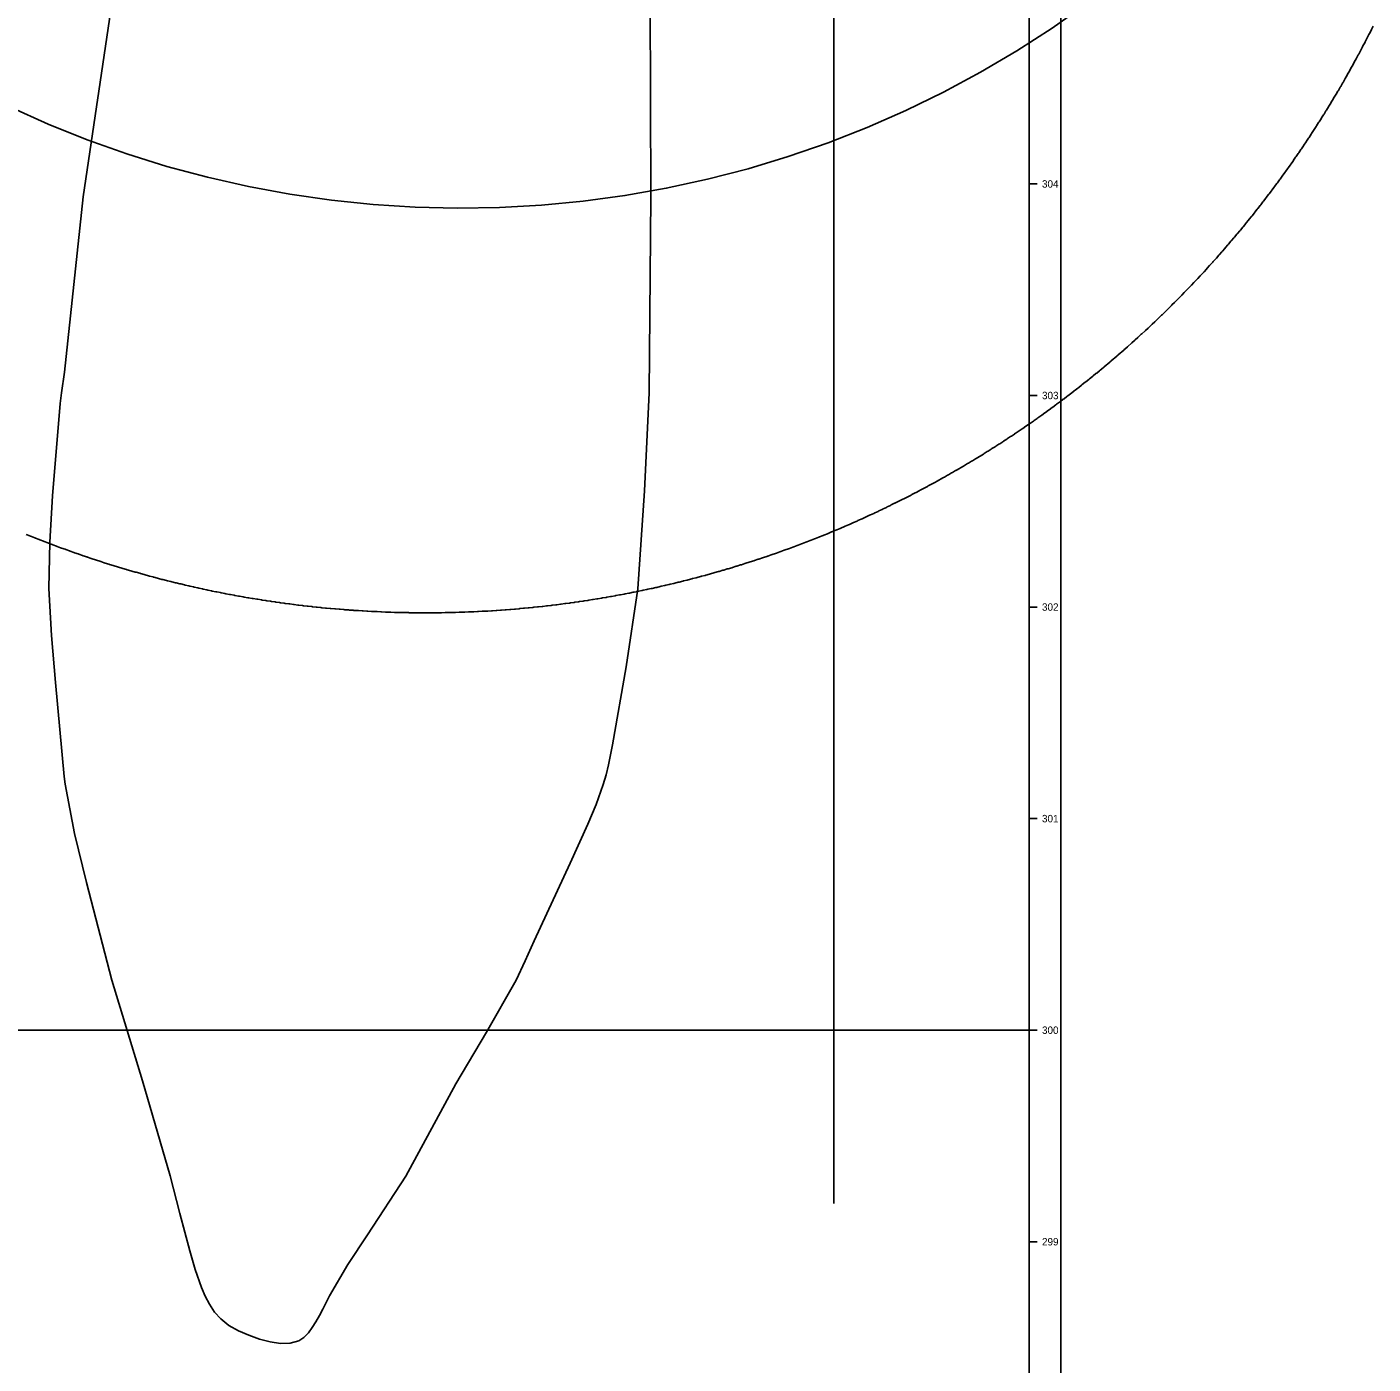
# Model space of a CAD drawing. Extents: x 468834 to 503362, y 294936 to 320859.
# Drawn here: x 496187 to 502549, y 298422 to 304742 of the extents above; entities that cross this region are included whole.
import ezdxf

# ---------------------------------------------------------------- set-up
doc = ezdxf.new("R2010")
doc.units = 0
for name, color, linetype in [('1020106_TIN16_5 km radiuss ap lidlauku Rīga kontrolpunktu', 7, 'Continuous'), ('1020107_TIN17_5 km radiuss ap lidlauku Rīga slieksniem', 7, 'Continuous'), ('1020110_TIN110_Lidmašīnu radīto trokšņu robežlieluma pārsnieguma teritorija', 7, 'Continuous'), ('ramis', 7, 'Continuous')]:
    doc.layers.add(name, color=color, linetype=linetype)

msp = doc.modelspace()

# ---------------------------------------------------------------- linework, layer by layer
at = {"layer": '1020106_TIN16_5 km radiuss ap lidlauku Rīga kontrolpunktu'}
msp.add_lwpolyline([(501194.7, 304851), (501032.1, 304736.8), (500865, 304629.1), (500693.8, 304528.1), (500518.8, 304434.1), (500340.1, 304347.1), (500158.1, 304267.2), (499973.1, 304194.7), (499785.3, 304129.5), (499595.1, 304071.9), (499402.7, 304021.9), (499208.6, 303979.6), (499012.9, 303945), (498815.9, 303918.2), (498618.1, 303899.3), (498419.7, 303888.3), (498220.9, 303885.1), (498022.3, 303889.9), (497823.9, 303902.6), (497626.2, 303923.1), (497429.5, 303951.5), (497234.1, 303987.7), (497040.3, 304031.6), (496848.3, 304083.2), (496658.6, 304142.3), (496471.4, 304209), (496287, 304283.1), (496105.6, 304364.4)], dxfattribs=at)
at = {"layer": '1020107_TIN17_5 km radiuss ap lidlauku Rīga slieksniem'}
msp.add_lwpolyline([(502549.4, 304745.6), (502541.6, 304730), (502539.6, 304726.1), (502531.7, 304710.5), (502529.7, 304706.6), (502521.8, 304691.1), (502519.8, 304687.2), (502511.8, 304671.7), (502509.8, 304667.8), (502501.7, 304652.3), (502499.7, 304648.5), (502491.6, 304633), (502489.5, 304629.2), (502481.3, 304613.8), (502479.2, 304609.9), (502471, 304594.6), (502468.9, 304590.7), (502460.6, 304575.4), (502458.5, 304571.6), (502450, 304556.3), (502447.9, 304552.5), (502439.5, 304537.2), (502437.3, 304533.4), (502428.8, 304518.2), (502426.6, 304514.4), (502418, 304499.2), (502415.9, 304495.4), (502407.2, 304480.2), (502405.5, 304477.3), (502405, 304476.5), (502396.3, 304461.4), (502394.1, 304457.6), (502385.3, 304442.5), (502383.1, 304438.8), (502374.2, 304423.7), (502372, 304420), (502363, 304405), (502360.8, 304401.2), (502351.8, 304386.3), (502349.5, 304382.6), (502340.5, 304367.6), (502338.2, 304363.9), (502329.1, 304349), (502326.8, 304345.3), (502317.6, 304330.5), (502315.3, 304326.8), (502306, 304312), (502303.7, 304308.3), (502294.4, 304293.6), (502292, 304289.9), (502282.6, 304275.2), (502280.3, 304271.5), (502270.8, 304256.8), (502268.4, 304253.2), (502258.9, 304238.5), (502256.5, 304234.9), (502246.9, 304220.3), (502244.5, 304216.6), (502234.9, 304202.1), (502233, 304199.2), (502232.5, 304198.5), (502222.8, 304184), (502220.3, 304180.3), (502210.6, 304165.9), (502208.1, 304162.3), (502198.3, 304147.9), (502195.8, 304144.3), (502185.9, 304129.9), (502183.4, 304126.3), (502173.5, 304112), (502171, 304108.4), (502160.9, 304094.1), (502158.4, 304090.5), (502148.3, 304076.3), (502145.8, 304072.7), (502135.7, 304058.5), (502133.1, 304055), (502122.9, 304040.8), (502120.3, 304037.3), (502110.1, 304023.2), (502107.5, 304019.7), (502097.2, 304005.6), (502094.6, 304002.1), (502084.2, 303988.1), (502081.6, 303984.6), (502071.1, 303970.6), (502068.5, 303967.1), (502058, 303953.2), (502055.3, 303949.7), (502044.8, 303935.8), (502042.7, 303933.1), (502042.1, 303932.4), (502031.5, 303918.5), (502028.8, 303915.1), (502018.1, 303901.3), (502015.4, 303897.8), (502004.7, 303884.1), (502002, 303880.7), (501991.2, 303867), (501988.4, 303863.5), (501977.6, 303849.9), (501974.8, 303846.5), (501963.9, 303832.9), (501961.2, 303829.5), (501950.2, 303815.9), (501947.4, 303812.6), (501936.4, 303799.1), (501933.6, 303795.7), (501922.5, 303782.2), (501919.7, 303778.9), (501908.5, 303765.5), (501905.7, 303762.1), (501894.5, 303748.8), (501891.7, 303745.4), (501880.4, 303732.1), (501877.5, 303728.8), (501866.2, 303715.5), (501863.4, 303712.2), (501852, 303699), (501849.1, 303695.7), (501837.6, 303682.5), (501835.4, 303680), (501834.8, 303679.3), (501823.2, 303666.2), (501820.4, 303662.9), (501808.8, 303649.8), (501805.9, 303646.6), (501794.2, 303633.6), (501791.3, 303630.3), (501779.6, 303617.3), (501776.7, 303614.1), (501765, 303601.2), (501762, 303598), (501750.2, 303585.1), (501747.3, 303581.9), (501735.4, 303569.1), (501732.4, 303565.9), (501720.5, 303553.2), (501717.5, 303550), (501705.6, 303537.3), (501702.6, 303534.1), (501690.5, 303521.5), (501687.5, 303518.3), (501675.4, 303505.7), (501672.4, 303502.6), (501660.3, 303490), (501657.2, 303486.9), (501645, 303474.4), (501642, 303471.3), (501629.7, 303458.9), (501626.7, 303455.7), (501614.4, 303443.4), (501611.9, 303440.9), (501611.3, 303440.3), (501598.9, 303427.9), (501595.8, 303424.9), (501583.4, 303412.6), (501580.3, 303409.5), (501567.9, 303397.3), (501564.7, 303394.3), (501552.2, 303382.1), (501549.1, 303379.1), (501536.5, 303366.9), (501533.4, 303363.9), (501520.8, 303351.9), (501517.6, 303348.9), (501504.9, 303336.9), (501501.8, 303333.9), (501489, 303321.9), (501485.8, 303318.9), (501473.1, 303307), (501469.9, 303304.1), (501457, 303292.2), (501453.8, 303289.3), (501441, 303277.5), (501437.7, 303274.6), (501424.8, 303262.9), (501421.6, 303259.9), (501408.6, 303248.3), (501405.3, 303245.4), (501392.3, 303233.7), (501389, 303230.8), (501375.9, 303219.3), (501373.4, 303217), (501372.7, 303216.4), (501359.5, 303204.9), (501356.2, 303202.1), (501343.1, 303190.6), (501339.8, 303187.8), (501326.5, 303176.4), (501323.2, 303173.5), (501309.9, 303162.2), (501306.6, 303159.4), (501293.3, 303148.1), (501289.9, 303145.3), (501276.6, 303134.1), (501273.2, 303131.3), (501259.8, 303120.2), (501256.4, 303117.4), (501242.9, 303106.3), (501239.6, 303103.5), (501226, 303092.5), (501222.6, 303089.8), (501209.1, 303078.8), (501205.7, 303076.1), (501192.1, 303065.1), (501188.6, 303062.4), (501175, 303051.6), (501171.5, 303048.9), (501157.8, 303038.1), (501154.4, 303035.4), (501140.6, 303024.6), (501137.2, 303022), (501123.4, 303011.3), (501120.7, 303009.2), (501119.9, 303008.6), (501106.1, 302998), (501102.6, 302995.4), (501088.7, 302984.8), (501085.2, 302982.2), (501071.3, 302971.7), (501067.8, 302969.1), (501053.8, 302958.7), (501050.3, 302956.1), (501036.2, 302945.7), (501032.7, 302943.1), (501018.6, 302932.8), (501015.1, 302930.2), (501001, 302920), (500997.4, 302917.4), (500983.3, 302907.3), (500979.7, 302904.7), (500965.5, 302894.6), (500961.9, 302892.1), (500947.7, 302882), (500944.1, 302879.5), (500929.8, 302869.5), (500926.2, 302867), (500911.9, 302857.1), (500908.3, 302854.6), (500893.9, 302844.7), (500890.3, 302842.3), (500875.8, 302832.5), (500872.2, 302830), (500857.7, 302820.3), (500854.9, 302818.4), (500854.1, 302817.8), (500839.6, 302808.2), (500836, 302805.7), (500821.4, 302796.1), (500817.8, 302793.7), (500803.2, 302784.2), (500799.5, 302781.8), (500784.8, 302772.3), (500781.2, 302769.9), (500766.5, 302760.5), (500762.8, 302758.2), (500748.1, 302748.8), (500744.4, 302746.5), (500729.6, 302737.2), (500725.9, 302734.8), (500711.1, 302725.6), (500707.4, 302723.3), (500692.6, 302714.1), (500688.8, 302711.9), (500674, 302702.7), (500670.2, 302700.5), (500655.3, 302691.4), (500651.6, 302689.2), (500636.6, 302680.2), (500632.8, 302678), (500617.8, 302669.1), (500614.1, 302666.8), (500599, 302658), (500595.3, 302655.8), (500580.2, 302647), (500577.2, 302645.3), (500576.4, 302644.8), (500561.3, 302636.1), (500557.5, 302633.9), (500542.3, 302625.3), (500538.5, 302623.1), (500523.3, 302614.6), (500519.5, 302612.4), (500504.3, 302603.9), (500500.5, 302601.8), (500485.2, 302593.3), (500481.4, 302591.2), (500466.1, 302582.9), (500462.3, 302580.8), (500446.9, 302572.5), (500443.1, 302570.4), (500427.7, 302562.1), (500423.8, 302560.1), (500408.4, 302551.9), (500404.6, 302549.9), (500389.1, 302541.8), (500385.2, 302539.7), (500369.8, 302531.7), (500365.9, 302529.7), (500350.4, 302521.7), (500346.5, 302519.7), (500330.9, 302511.8), (500327, 302509.9), (500311.4, 302502), (500307.5, 302500.1), (500291.9, 302492.3), (500288.8, 302490.8), (500288, 302490.4), (500272.3, 302482.7), (500268.4, 302480.7), (500252.7, 302473.1), (500248.8, 302471.2), (500233.1, 302463.6), (500229.1, 302461.7), (500213.4, 302454.2), (500209.4, 302452.4), (500193.6, 302444.9), (500189.7, 302443.1), (500173.8, 302435.7), (500169.9, 302433.9), (500154, 302426.6), (500150.1, 302424.8), (500134.2, 302417.6), (500130.2, 302415.8), (500114.3, 302408.6), (500110.3, 302406.8), (500094.3, 302399.8), (500090.3, 302398), (500074.4, 302391), (500070.4, 302389.2), (500054.4, 302382.3), (500050.3, 302380.6), (500034.3, 302373.7), (500030.3, 302372), (500014.2, 302365.2), (500010.2, 302363.5), (499994.1, 302356.8), (499990.9, 302355.4), (499990.1, 302355.1), (499973.9, 302348.4), (499969.9, 302346.8), (499953.7, 302340.2), (499949.7, 302338.5), (499933.5, 302332), (499929.5, 302330.4), (499913.2, 302323.9), (499909.2, 302322.3), (499892.9, 302315.9), (499888.9, 302314.4), (499872.6, 302308), (499868.5, 302306.5), (499852.2, 302300.2), (499848.2, 302298.7), (499831.8, 302292.5), (499827.7, 302291), (499811.4, 302284.9), (499807.3, 302283.4), (499790.9, 302277.3), (499786.8, 302275.8), (499770.4, 302269.9), (499766.3, 302268.4), (499749.9, 302262.5), (499745.8, 302261.1), (499729.3, 302255.3), (499725.2, 302253.8), (499708.7, 302248.1), (499704.6, 302246.6), (499688.1, 302241), (499684.8, 302239.9), (499683.9, 302239.6), (499667.4, 302234), (499663.3, 302232.6), (499646.7, 302227.1), (499642.6, 302225.7), (499626, 302220.2), (499621.8, 302218.9), (499605.2, 302213.5), (499601.1, 302212.2), (499584.5, 302206.9), (499580.3, 302205.6), (499563.7, 302200.3), (499559.5, 302199), (499542.8, 302193.9), (499538.6, 302192.6), (499521.9, 302187.5), (499517.8, 302186.2), (499501.1, 302181.2), (499496.9, 302180), (499480.1, 302175), (499475.9, 302173.8), (499459.2, 302168.9), (499455, 302167.7), (499438.2, 302162.9), (499434, 302161.7), (499417.2, 302157), (499413, 302155.8), (499396.2, 302151.2), (499392, 302150), (499375.1, 302145.5), (499371.8, 302144.6), (499370.9, 302144.3), (499354.1, 302139.8), (499349.8, 302138.7), (499333, 302134.3), (499328.7, 302133.2), (499311.8, 302128.8), (499307.6, 302127.8), (499290.7, 302123.5), (499286.5, 302122.4), (499269.5, 302118.2), (499265.3, 302117.2), (499248.3, 302113), (499244.1, 302112), (499227.1, 302108), (499222.9, 302106.9), (499205.9, 302103), (499201.6, 302102), (499184.6, 302098.1), (499180.4, 302097.1), (499163.3, 302093.3), (499159.1, 302092.3), (499142, 302088.5), (499137.8, 302087.6), (499120.7, 302083.9), (499116.4, 302083), (499099.4, 302079.4), (499095.1, 302078.5), (499078, 302075), (499073.7, 302074.1), (499056.6, 302070.6), (499053.2, 302070), (499052.3, 302069.8), (499035.2, 302066.4), (499030.9, 302065.5), (499013.8, 302062.2), (499009.5, 302061.4), (498992.4, 302058.2), (498988.1, 302057.4), (498970.9, 302054.2), (498966.6, 302053.4), (498949.4, 302050.3), (498945.1, 302049.6), (498928, 302046.6), (498923.7, 302045.8), (498906.4, 302042.9), (498902.1, 302042.2), (498884.9, 302039.3), (498880.6, 302038.6), (498863.4, 302035.8), (498859.1, 302035.1), (498841.8, 302032.4), (498837.5, 302031.7), (498820.3, 302029.1), (498816, 302028.4), (498798.7, 302025.9), (498794.4, 302025.2), (498777.1, 302022.7), (498772.8, 302022.1), (498755.5, 302019.7), (498751.2, 302019.1), (498733.9, 302016.8), (498730.5, 302016.3), (498729.6, 302016.2), (498712.3, 302014), (498707.9, 302013.4), (498690.6, 302011.2), (498686.3, 302010.7), (498669, 302008.6), (498664.6, 302008), (498647.3, 302006), (498643, 302005.5), (498625.6, 302003.5), (498621.3, 302003.1), (498603.9, 302001.2), (498599.6, 302000.7), (498582.2, 301998.9), (498577.9, 301998.5), (498560.5, 301996.7), (498556.2, 301996.3), (498538.8, 301994.7), (498534.5, 301994.3), (498517.1, 301992.7), (498512.7, 301992.3), (498495.3, 301990.8), (498491, 301990.4), (498473.6, 301989), (498469.2, 301988.6), (498451.8, 301987.3), (498447.5, 301987), (498430.1, 301985.7), (498425.7, 301985.4), (498408.3, 301984.2), (498404.9, 301983.9), (498404, 301983.9), (498386.6, 301982.7), (498382.2, 301982.5), (498364.8, 301981.4), (498360.4, 301981.2), (498343, 301980.2), (498338.6, 301980), (498321.2, 301979.1), (498316.9, 301978.9), (498299.4, 301978), (498295.1, 301977.8), (498277.6, 301977.1), (498273.3, 301976.9), (498255.8, 301976.2), (498251.5, 301976.1), (498234, 301975.5), (498229.7, 301975.4), (498212.2, 301974.8), (498207.8, 301974.7), (498190.4, 301974.3), (498186, 301974.2), (498168.6, 301973.8), (498164.2, 301973.7), (498146.8, 301973.4), (498142.4, 301973.4), (498125, 301973.2), (498120.6, 301973.1), (498103.1, 301973), (498098.8, 301973), (498081.3, 301972.9), (498077.9, 301972.9), (498077, 301972.9), (498059.5, 301972.9), (498055.1, 301972.9), (498037.7, 301973), (498033.3, 301973.1), (498015.9, 301973.2), (498011.5, 301973.3), (497994.1, 301973.5), (497989.7, 301973.6), (497972.3, 301973.9), (497967.9, 301974), (497950.4, 301974.4), (497946.1, 301974.5), (497928.6, 301975), (497924.3, 301975.1), (497906.8, 301975.7), (497902.5, 301975.8), (497885, 301976.4), (497880.7, 301976.6), (497863.2, 301977.3), (497858.9, 301977.5), (497841.4, 301978.3), (497837.1, 301978.5), (497819.6, 301979.3), (497815.3, 301979.5), (497797.9, 301980.5), (497793.5, 301980.7), (497776.1, 301981.7), (497771.7, 301982), (497754.3, 301983.1), (497750.9, 301983.3), (497749.9, 301983.3), (497732.5, 301984.5), (497728.2, 301984.8), (497710.8, 301986), (497706.4, 301986.3), (497689, 301987.7), (497684.7, 301988), (497667.3, 301989.4), (497662.9, 301989.7), (497645.5, 301991.2), (497641.2, 301991.6), (497623.8, 301993.1), (497619.4, 301993.5), (497602.1, 301995.1), (497597.7, 301995.5), (497580.3, 301997.2), (497576, 301997.6), (497558.6, 301999.4), (497554.3, 301999.9), (497536.9, 302001.7), (497532.6, 302002.2), (497515.3, 302004.1), (497510.9, 302004.6), (497493.6, 302006.6), (497489.2, 302007.1), (497471.9, 302009.1), (497467.6, 302009.7), (497450.3, 302011.8), (497445.9, 302012.4), (497428.6, 302014.6), (497425.2, 302015), (497424.3, 302015.1), (497407, 302017.4), (497402.7, 302018), (497385.4, 302020.4), (497381.1, 302021), (497363.8, 302023.4), (497359.5, 302024.1), (497342.2, 302026.6), (497337.9, 302027.2), (497320.6, 302029.8), (497316.3, 302030.5), (497299.1, 302033.1), (497294.7, 302033.8), (497277.5, 302036.6), (497273.2, 302037.3), (497256, 302040.1), (497251.7, 302040.8), (497234.5, 302043.7), (497230.2, 302044.4), (497213, 302047.4), (497208.7, 302048.1), (497191.5, 302051.2), (497187.2, 302052), (497170, 302055.1), (497165.7, 302055.9), (497148.6, 302059.1), (497144.3, 302059.9), (497127.1, 302063.2), (497122.8, 302064), (497105.7, 302067.3), (497102.3, 302068), (497101.4, 302068.2), (497084.3, 302071.6), (497080, 302072.5), (497062.9, 302075.9), (497058.7, 302076.8), (497041.6, 302080.4), (497037.3, 302081.3), (497020.2, 302084.9), (497016, 302085.9), (496998.9, 302089.6), (496994.7, 302090.5), (496977.6, 302094.3), (496973.4, 302095.3), (496956.4, 302099.1), (496952.1, 302100.1), (496935.1, 302104.1), (496930.9, 302105.1), (496913.9, 302109.1), (496909.6, 302110.1), (496892.7, 302114.2), (496888.4, 302115.2), (496871.5, 302119.4), (496867.2, 302120.4), (496850.3, 302124.7), (496846.1, 302125.7), (496829.2, 302130), (496824.9, 302131.1), (496808, 302135.5), (496803.8, 302136.6), (496786.9, 302141.1), (496783.6, 302142), (496782.7, 302142.2), (496765.9, 302146.7), (496761.7, 302147.9), (496744.8, 302152.5), (496740.6, 302153.6), (496723.8, 302158.3), (496719.6, 302159.5), (496702.8, 302164.3), (496698.6, 302165.5), (496681.8, 302170.3), (496677.7, 302171.5), (496660.9, 302176.4), (496656.7, 302177.6), (496640, 302182.6), (496635.8, 302183.9), (496619.1, 302188.9), (496614.9, 302190.2), (496598.2, 302195.3), (496594.1, 302196.6), (496577.4, 302201.8), (496573.2, 302203.1), (496556.6, 302208.3), (496552.4, 302209.7), (496535.8, 302215), (496531.7, 302216.3), (496515.1, 302221.8), (496510.9, 302223.1), (496494.4, 302228.6), (496490.2, 302230), (496473.7, 302235.5), (496470.4, 302236.6), (496469.6, 302236.9), (496453, 302242.5), (496448.9, 302244), (496432.4, 302249.7), (496428.3, 302251.1), (496411.8, 302256.9), (496407.7, 302258.3), (496391.2, 302264.2), (496387.1, 302265.6), (496370.7, 302271.5), (496366.6, 302273), (496350.2, 302279), (496346.1, 302280.5), (496329.8, 302286.6), (496325.7, 302288.1), (496309.3, 302294.2), (496305.2, 302295.8), (496288.9, 302302), (496284.9, 302303.5), (496268.6, 302309.8), (496264.5, 302311.4), (496248.2, 302317.7), (496244.2, 302319.3), (496227.9, 302325.7), (496223.9, 302327.3), (496207.7, 302333.8), (496203.6, 302335.4), (496187.5, 302342), (496183.4, 302343.6)], dxfattribs=at)
at = {"layer": '1020110_TIN110_Lidmašīnu radīto trokšņu robežlieluma pārsnieguma teritorija'}
msp.add_lwpolyline([(499132.9, 304863.3), (499135.7, 303937.8), (499127.6, 303012.2), (499106, 302549.1), (499074.8, 302086.7), (499019.3, 301717.3), (498954.7, 301349), (498935.2, 301254.4), (498923.9, 301207.5), (498910.9, 301161.2), (498877.1, 301066.4), (498838.1, 300973.3), (498754.4, 300789.1), (498584, 300421.6), (498542.3, 300328.2), (498498.6, 300235.9), (498358.2, 299990.1), (498213.5, 299746.2), (497977.3, 299310.5), (497796.2, 299032.4), (497704.2, 298892.8), (497616.2, 298743.9), (497600.5, 298713.2), (497584.9, 298682.1), (497569.2, 298651.3), (497552.8, 298621.6), (497535.5, 298593.9), (497516.8, 298568.9), (497496, 298547.9), (497472.6, 298532.2), (497431.5, 298520.5), (497385.3, 298519.8), (497336, 298527.1), (497285.5, 298540.1), (497235.1, 298557.7), (497186.6, 298579.2), (497141.5, 298604.8), (497102.4, 298635), (497073, 298667.9), (497049.1, 298704.4), (497029.1, 298743.4), (497011.8, 298784.2), (496982.3, 298869.2), (496956.7, 298956.5), (496909.8, 299134), (496863.5, 299311), (496732.7, 299761), (496588.1, 300236.7), (496468.1, 300697.7), (496411.6, 300929), (496366.9, 301162.3), (496363, 301199.5), (496321.5, 301643.6), (496302.3, 301865.7), (496289.8, 302087.9), (496295.4, 302306.5), (496307.9, 302525.3), (496343.2, 302961.9), (496350.4, 303013.4), (496363.9, 303110.3), (496453.1, 303938.9), (496589, 304864.4)], dxfattribs=at)
at = {"layer": 'ramis'}
for p, q in [((500923.3, 316660.3), (500923.3, 295086.2)), ((500923.3, 304000), (500961.5, 304000)), ((500923.3, 303000), (500961.5, 303000)), ((500923.3, 302000), (500961.5, 302000)), ((500923.3, 301000), (500961.5, 301000)), ((500923.3, 300000), (500961.5, 300000)), ((500923.3, 299000), (500961.5, 299000))]:
    msp.add_line(p, q, dxfattribs=at)
msp.add_lwpolyline([(501073.3, 316810.3), (468833.8, 316810.3), (468833.8, 294936.2), (501073.3, 294936.2)], close=True, dxfattribs=at)
for points in [[(500000, 299180.3), (500000, 316660.3)], [(482061.2, 300000), (500923.3, 300000)]]:
    msp.add_lwpolyline(points, dxfattribs=at)

# ---------------------------------------------------------------- texts
for s, p in [('304', (500984.5, 303982.6)), ('303', (500984.5, 302982.6)), ('302', (500984.5, 301982.6)), ('301', (500984.5, 300982.6)), ('300', (500984.5, 299982.6)), ('299', (500984.5, 298982.6))]:
    msp.add_text(s, height=35, dxfattribs=at).set_placement(p)

doc.saveas('drawing.dxf')
